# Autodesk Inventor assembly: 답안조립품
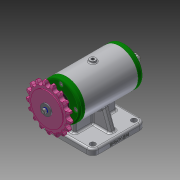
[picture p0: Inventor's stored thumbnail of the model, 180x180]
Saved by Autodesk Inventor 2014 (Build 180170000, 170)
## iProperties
Created: 2019-06
Part Number: 답안조립품
Document SubType Name: Assembly
Designer: OA55
Author: OA55
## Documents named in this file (11)
- C:\Users\OA55\Desktop\490604V1026\답안조립품.iam
- C:\Users\OA55\Desktop\490604V1026\본체.ipt
- C:\Users\OA55\Desktop\490604V1026\커버.ipt
- C:\Users\OA55\Desktop\490604V1026\베어링 6203.ipt
- C:\Users\OA55\Desktop\490604V1026\볼트 M4.ipt
- C:\Users\OA55\Desktop\490604V1026\오일 실 17 30 5.ipt
- C:\Users\OA55\Desktop\490604V1026\축.ipt
- C:\Users\OA55\Desktop\490604V1026\키 4x4x12.ipt
- C:\Users\OA55\Desktop\490604V1026\스프로킷.ipt
- C:\Users\OA55\Desktop\490604V1026\스프링와셔.ipt
- C:\Users\OA55\Desktop\490604V1026\평와셔.ipt
